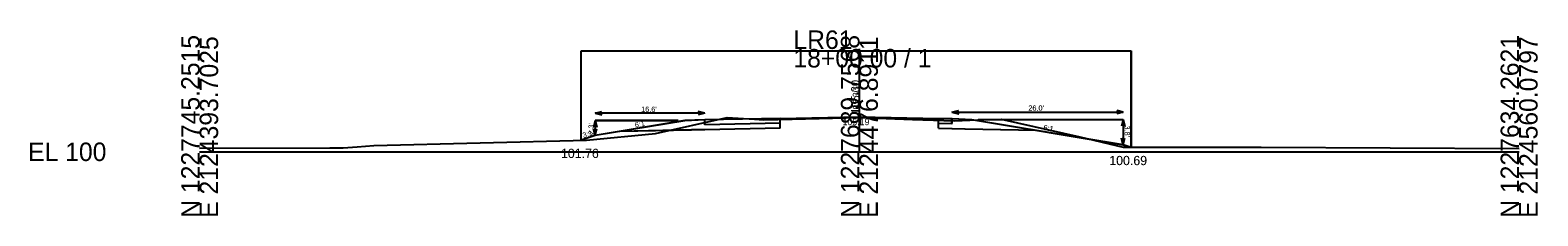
# Model space of a CAD drawing. Extents: x 2126751 to 2128979, y 1225108 to 1234639.
# Drawn here: x 2127750.9 to 2127979.4, y 1233107.5 to 1233135.6 of the extents above; entities that cross this region are included whole.
import ezdxf

# ---------------------------------------------------------------- set-up
doc = ezdxf.new("R2010")
doc.units = 0
for name, color, linetype in [('XS_CELL', 7, 'Continuous'), ('XS_M_DITCH', 7, 'Continuous'), ('XS_P_FINISHED_GRADE', 7, 'Continuous'), ('XS_P_FINISHED_GRADE_ELEV_TX', 7, 'Continuous'), ('XS_P_SUBGRADE_GRANULAR', 7, 'Continuous'), ('XS_P_SUBGRADE_LEVELING', 7, 'Continuous'), ('XS_P_SUBGRADE_PAVEMENT', 7, 'Continuous'), ('XS_P_TX_CLEARZONE', 7, 'Continuous'), ('XS_P_TX_DCH', 7, 'Continuous'), ('XS_P_TX_FS_BS', 7, 'Continuous'), ('XS_X_GROUND', 7, 'Continuous'), ('XS_X_GROUND_TX', 7, 'Continuous')]:
    doc.layers.add(name, color=color, linetype=linetype)

msp = doc.modelspace()

# ---------------------------------------------------------------- linework, layer by layer
at = {"layer": 'XS_CELL'}
for p, q in [((2127876.61, 1233117.21), (2127876.61, 1233132.78)), ((2127776.61, 1233117.21), (2127876.61, 1233117.21)), ((2127876.61, 1233117.21), (2127976.61, 1233117.21))]:
    msp.add_line(p, q, dxfattribs=at)
at = {"layer": 'XS_M_DITCH'}
for p, q in [((2127834.45, 1233118.97), (2127834.45, 1233132.51)), ((2127834.45, 1233132.51), (2127917.77, 1233132.51)), ((2127834.45, 1233118.97), (2127834.45, 1233132.51)), ((2127834.45, 1233132.51), (2127917.79, 1233132.51)), ((2127917.77, 1233132.51), (2127917.77, 1233117.89)), ((2127917.79, 1233132.51), (2127917.79, 1233117.89))]:
    msp.add_line(p, q, dxfattribs=at)
at = {"layer": 'XS_P_FINISHED_GRADE'}
for p, q in [((2127850.16, 1233121.93), (2127836.55, 1233119.67)), ((2127850.15, 1233121.92), (2127836.55, 1233119.67)), ((2127853.16, 1233122.04), (2127850.15, 1233121.92)), ((2127853.18, 1233122.05), (2127850.16, 1233121.93)), ((2127864.61, 1233122.27), (2127853.16, 1233122.04)), ((2127864.61, 1233122.27), (2127853.18, 1233122.05)), ((2127864.61, 1233122.27), (2127876.61, 1233122.51)), ((2127864.61, 1233122.27), (2127876.61, 1233122.51)), ((2127876.61, 1233122.51), (2127888.61, 1233122.27)), ((2127876.61, 1233122.51), (2127888.61, 1233122.27)), ((2127888.61, 1233122.27), (2127890.61, 1233122.23)), ((2127888.61, 1233122.27), (2127890.66, 1233122.23)), ((2127890.61, 1233122.23), (2127893.61, 1233122.11)), ((2127890.66, 1233122.23), (2127893.66, 1233122.11)), ((2127893.61, 1233122.11), (2127916.61, 1233118.28)), ((2127893.66, 1233122.11), (2127916.61, 1233118.29)), ((2127836.55, 1233119.67), (2127834.45, 1233118.97)), ((2127836.55, 1233119.67), (2127834.45, 1233118.97)), ((2127916.61, 1233118.29), (2127917.79, 1233117.89)), ((2127916.61, 1233118.28), (2127917.77, 1233117.89))]:
    msp.add_line(p, q, dxfattribs=at)
at = {"layer": 'XS_P_SUBGRADE_GRANULAR'}
for p, q in [((2127864.61, 1233120.77), (2127853.16, 1233120.54)), ((2127864.61, 1233120.77), (2127853.18, 1233120.55)), ((2127864.61, 1233120.77), (2127864.61, 1233121.52)), ((2127864.61, 1233120.77), (2127864.61, 1233121.52)), ((2127888.61, 1233120.77), (2127888.61, 1233121.52)), ((2127888.61, 1233120.77), (2127888.61, 1233121.52)), ((2127888.61, 1233120.77), (2127890.61, 1233120.73)), ((2127888.61, 1233120.77), (2127890.66, 1233120.73)), ((2127851.16, 1233120.5), (2127840.28, 1233120.29)), ((2127851.18, 1233120.51), (2127840.29, 1233120.29)), ((2127853.16, 1233120.54), (2127851.16, 1233120.5)), ((2127853.18, 1233120.55), (2127851.18, 1233120.51)), ((2127890.61, 1233120.73), (2127892.61, 1233120.69)), ((2127890.66, 1233120.73), (2127892.66, 1233120.69)), ((2127892.61, 1233120.69), (2127903.43, 1233120.48)), ((2127892.66, 1233120.69), (2127903.48, 1233120.48))]:
    msp.add_line(p, q, dxfattribs=at)
at = {"layer": 'XS_P_SUBGRADE_LEVELING'}
for p, q in [((2127864.61, 1233122.27), (2127864.61, 1233122.12)), ((2127864.61, 1233122.27), (2127864.61, 1233122.12)), ((2127864.61, 1233122.12), (2127866.41, 1233122.16)), ((2127864.61, 1233122.12), (2127866.41, 1233122.16)), ((2127866.41, 1233122.16), (2127876.64, 1233122.4)), ((2127866.41, 1233122.16), (2127876.64, 1233122.4)), ((2127876.64, 1233122.4), (2127884.68, 1233122.12)), ((2127876.64, 1233122.4), (2127884.68, 1233122.12)), ((2127884.68, 1233122.12), (2127888.61, 1233121.99)), ((2127884.68, 1233122.12), (2127888.61, 1233121.99)), ((2127888.61, 1233122.27), (2127888.61, 1233121.99)), ((2127888.61, 1233122.27), (2127888.61, 1233121.99))]:
    msp.add_line(p, q, dxfattribs=at)
at = {"layer": 'XS_P_SUBGRADE_PAVEMENT'}
for p, q in [((2127853.16, 1233121.29), (2127853.16, 1233122.04)), ((2127864.61, 1233121.52), (2127853.16, 1233121.29)), ((2127853.18, 1233121.3), (2127853.18, 1233122.05)), ((2127864.61, 1233121.52), (2127853.18, 1233121.3)), ((2127864.61, 1233121.52), (2127864.61, 1233122.12)), ((2127888.61, 1233121.52), (2127888.61, 1233121.99)), ((2127888.61, 1233121.52), (2127888.61, 1233121.99)), ((2127888.61, 1233121.52), (2127890.61, 1233121.48)), ((2127888.61, 1233121.52), (2127890.66, 1233121.48)), ((2127890.61, 1233121.48), (2127890.61, 1233122.23)), ((2127890.66, 1233121.48), (2127890.66, 1233122.23))]:
    msp.add_line(p, q, dxfattribs=at)
at = {"layer": 'XS_P_TX_CLEARZONE'}
for p, q in [((2127836.55, 1233123.05), (2127837.55, 1233123.3)), ((2127836.55, 1233123.04), (2127837.55, 1233123.29)), ((2127853.16, 1233123.04), (2127852.16, 1233123.29)), ((2127853.18, 1233123.05), (2127852.17, 1233123.3)), ((2127890.61, 1233123.23), (2127891.61, 1233123.48)), ((2127890.61, 1233123.23), (2127891.61, 1233122.98)), ((2127890.61, 1233123.23), (2127916.61, 1233123.23)), ((2127890.66, 1233123.23), (2127891.66, 1233123.48)), ((2127890.66, 1233123.23), (2127891.66, 1233122.98)), ((2127890.66, 1233123.23), (2127916.61, 1233123.23)), ((2127916.61, 1233123.23), (2127915.61, 1233123.48)), ((2127916.61, 1233123.23), (2127915.61, 1233123.48)), ((2127916.61, 1233123.23), (2127915.61, 1233122.98)), ((2127916.61, 1233123.23), (2127915.61, 1233122.98)), ((2127836.55, 1233121.93), (2127836.3, 1233120.93)), ((2127836.55, 1233121.92), (2127836.3, 1233120.92)), ((2127836.55, 1233123.05), (2127837.55, 1233122.8)), ((2127853.18, 1233123.05), (2127836.55, 1233123.05)), ((2127836.55, 1233123.04), (2127837.55, 1233122.79)), ((2127853.16, 1233123.04), (2127836.55, 1233123.04)), ((2127836.55, 1233121.93), (2127836.8, 1233120.93)), ((2127836.55, 1233121.93), (2127836.55, 1233119.67)), ((2127849.16, 1233121.93), (2127836.55, 1233121.93)), ((2127836.55, 1233121.92), (2127836.8, 1233120.92)), ((2127836.55, 1233121.92), (2127836.55, 1233119.67)), ((2127849.14, 1233121.92), (2127836.55, 1233121.92)), ((2127853.16, 1233123.04), (2127852.16, 1233122.79)), ((2127853.18, 1233123.05), (2127852.17, 1233122.8)), ((2127894.61, 1233122.11), (2127916.61, 1233122.11)), ((2127894.66, 1233122.11), (2127916.61, 1233122.11)), ((2127916.61, 1233122.11), (2127916.36, 1233121.11)), ((2127916.61, 1233122.11), (2127916.36, 1233121.11)), ((2127916.61, 1233122.11), (2127916.61, 1233118.28)), ((2127916.61, 1233122.11), (2127916.86, 1233121.11)), ((2127916.61, 1233122.11), (2127916.61, 1233118.29)), ((2127916.61, 1233122.11), (2127916.86, 1233121.11)), ((2127836.55, 1233119.67), (2127836.3, 1233120.67)), ((2127836.55, 1233119.67), (2127836.3, 1233120.67)), ((2127836.55, 1233119.67), (2127836.8, 1233120.67)), ((2127836.55, 1233119.67), (2127836.8, 1233120.67)), ((2127916.61, 1233118.29), (2127916.36, 1233119.29)), ((2127916.61, 1233118.28), (2127916.36, 1233119.28)), ((2127916.61, 1233118.29), (2127916.86, 1233119.29)), ((2127916.61, 1233118.28), (2127916.86, 1233119.28))]:
    msp.add_line(p, q, dxfattribs=at)
at = {"layer": 'XS_X_GROUND'}
for p, q in [((2127845.68, 1233119.99), (2127856.55, 1233122.4)), ((2127856.55, 1233122.4), (2127860.7, 1233122.14)), ((2127860.7, 1233122.14), (2127862.15, 1233122.06)), ((2127862.15, 1233122.06), (2127866.41, 1233122.16)), ((2127866.41, 1233122.16), (2127876.64, 1233122.4)), ((2127876.64, 1233122.4), (2127884.68, 1233122.12)), ((2127884.68, 1233122.12), (2127890.98, 1233121.91)), ((2127890.98, 1233121.91), (2127894.57, 1233122.04)), ((2127894.57, 1233122.04), (2127898.11, 1233122.17)), ((2127898.11, 1233122.17), (2127910.03, 1233119.46)), ((2127803.02, 1233118.18), (2127835.27, 1233118.99)), ((2127835.27, 1233118.99), (2127845.68, 1233119.99)), ((2127910.03, 1233119.46), (2127916.6, 1233117.9)), ((2127776.61, 1233117.77), (2127796.32, 1233117.81)), ((2127796.32, 1233117.81), (2127797.84, 1233117.81)), ((2127797.84, 1233117.81), (2127798.38, 1233117.82)), ((2127798.38, 1233117.82), (2127800.46, 1233117.98)), ((2127800.46, 1233117.98), (2127803.02, 1233118.18)), ((2127916.6, 1233117.9), (2127937.5, 1233117.89)), ((2127937.5, 1233117.89), (2127976.61, 1233117.73))]:
    msp.add_line(p, q, dxfattribs=at)

# ---------------------------------------------------------------- texts
at = {"layer": 'XS_CELL'}
for s, p in [('N 1227745.2515', (2127776.61, 1233107.21)), ('E 2124393.7025', (2127779.41, 1233107.21)), ('N 1227689.7568', (2127876.61, 1233107.21)), ('E 2124476.8911', (2127879.41, 1233107.21)), ('N 1227634.2621', (2127976.61, 1233107.21)), ('E 2124560.0797', (2127979.41, 1233107.21))]:
    msp.add_text(s, height=2.8, rotation=90, dxfattribs=at).set_placement(p)
for s, p in [('LR61', (2127866.61, 1233132.78)), ('18+00.00 / 1', (2127866.61, 1233129.98)), ('EL 100', (2127750.61, 1233115.81))]:
    msp.add_text(s, height=2.8, dxfattribs=at).set_placement(p)
at = {"layer": 'XS_P_FINISHED_GRADE_ELEV_TX'}
for height in [1.25, 1]:
    msp.add_text(' 105.30', height=height, rotation=90, dxfattribs=at).set_placement((2127876.61, 1233122.51))
at = {"layer": 'XS_P_TX_CLEARZONE'}
for s, p in [("16.6'", (2127843.53, 1233123.24)), ("16.6'", (2127843.53, 1233123.25)), ("26.0'", (2127902.21, 1233123.43)), ("26.0'", (2127902.23, 1233123.43))]:
    msp.add_text(s, height=0.8, dxfattribs=at).set_placement(p)
for s, rotation, p in [("2.3'", 90, (2127836.35, 1233119.8)), ("2.3'", 90, (2127836.35, 1233119.8)), ("3.8'", 270, (2127916.81, 1233121.19)), ("3.8'", 270, (2127916.81, 1233121.19))]:
    msp.add_text(s, height=0.8, rotation=rotation, dxfattribs=at).set_placement(p)
at = {"layer": 'XS_P_TX_DCH'}
for s, p in [('101.76', (2127831.38, 1233116.27)), ('101.76', (2127831.38, 1233116.27)), ('100.69', (2127914.48, 1233115.19)), ('100.69', (2127914.5, 1233115.19))]:
    msp.add_text(s, height=1.4, dxfattribs=at).set_placement(p)
at = {"layer": 'XS_P_TX_FS_BS'}
for s, rotation, p in [('6:1', 9.4211, (2127842.63, 1233120.88)), ('6:1', 9.4207, (2127842.63, 1233120.88)), ('6:1', 350.5377, (2127904.45, 1233120.51)), ('6:1', 350.5377, (2127904.48, 1233120.51)), ('3:1', 18.3587, (2127834.79, 1233119.29)), ('3:1', 18.3579, (2127834.79, 1233119.29))]:
    msp.add_text(s, height=0.8, rotation=rotation, dxfattribs=at).set_placement(p)
at = {"layer": 'XS_X_GROUND_TX'}
msp.add_text('105.19', height=1, dxfattribs=at).set_placement((2127874.05, 1233121.24))

doc.saveas('drawing.dxf')
